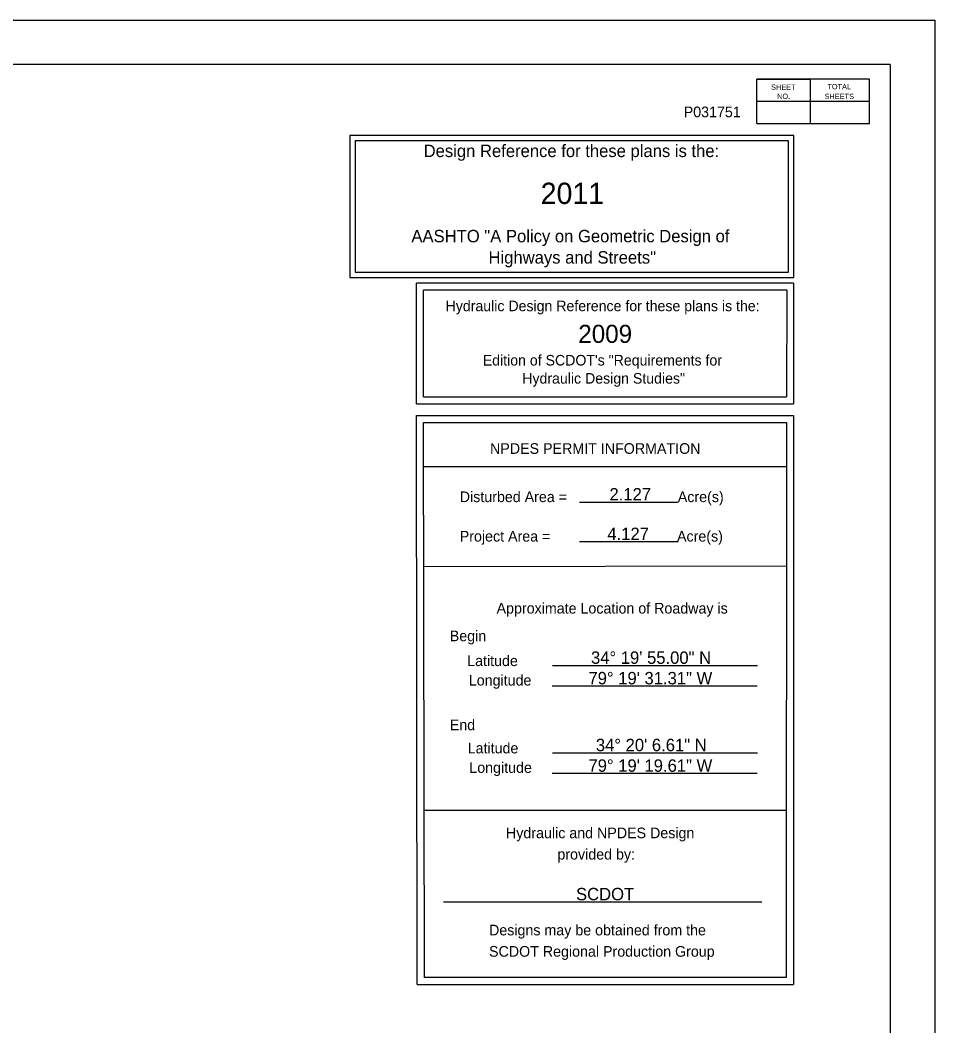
# Model space of a CAD drawing. Extents: x 178032 to 180477, y 178203 to 180757.
# Drawn here: x 179313 to 179828, y 178946 to 179513 of the extents above; entities that cross this region are included whole.
import ezdxf

# ---------------------------------------------------------------- set-up
doc = ezdxf.new("R2010")
doc.units = 0
for name, color, linetype in [('RD_SHT_Bndy', 7, 'Continuous'), ('RD_SHT_IplotShp', 7, 'Continuous'), ('RD_SHT_Snap', 7, 'Continuous'), ('RD_SHT_TX', 7, 'Continuous'), ('RD_TX_TitleSht', 7, 'Continuous')]:
    doc.layers.add(name, color=color, linetype=linetype)

msp = doc.modelspace()

# ---------------------------------------------------------------- linework, layer by layer
at = {"layer": 'RD_SHT_Bndy'}
for p, q in [((178048.25, 179512.54), (179808.23, 179512.54)), ((179803.28, 179487.54), (178128.38, 179487.54)), ((179803.38, 178437.54), (179803.38, 179487.59)), ((179791.53, 179479.34), (179728.03, 179479.34)), ((179728.03, 179454.34), (179728.03, 179479.34)), ((179728.03, 179479.34), (179758.03, 179479.34)), ((179758.03, 179479.34), (179758.03, 179454.34)), ((179791.53, 179454.34), (179791.53, 179479.34)), ((179728.4, 179466.84), (179791.18, 179466.84)), ((179728.03, 179454.34), (179791.53, 179454.34)), ((179536.35, 179296.45), (179536.28, 179364.44)), ((179748.8, 179364.44), (179536.28, 179364.44)), ((179748.8, 179364.44), (179748.78, 179296.5)), ((179540.32, 179300.4), (179540.23, 179360.5)), ((179744.88, 179360.5), (179540.23, 179360.5)), ((179744.88, 179360.5), (179744.85, 179300.45)), ((179540.32, 179300.4), (179744.85, 179300.45)), ((179536.35, 179296.45), (179748.78, 179296.5)), ((179536.35, 179289.82), (179748.78, 179289.87)), ((179536.72, 178969.44), (179536.35, 179289.82)), ((179748.78, 179289.87), (179748.7, 178969.44)), ((179540.33, 179285.82), (179744.84, 179285.99)), ((179540.8, 178973.38), (179540.33, 179285.82)), ((179744.84, 179285.99), (179744.67, 178973.3)), ((179540.48, 179261.07), (179744.8, 179261.04)), ((179628.25, 179241.09), (179683.8, 179241.09)), ((179628.25, 179218.86), (179683.8, 179218.86)), ((179540.45, 179204.9), (179744.66, 179205.17)), ((179612.97, 179149.13), (179728.52, 179149.13)), ((179612.77, 179137.54), (179728.33, 179137.54)), ((179612.97, 179099.91), (179728.52, 179099.91)), ((179612.77, 179088.32), (179728.33, 179088.32)), ((179744.77, 179067.32), (179540.66, 179067.32)), ((179551.52, 179015.91), (179730.96, 179015.91)), ((179744.67, 178973.3), (179540.8, 178973.38))]:
    msp.add_line(p, q, dxfattribs=at)
msp.add_lwpolyline([(179536.72, 178969.44), (179748.7, 178969.44)], dxfattribs=at)
at = {"layer": 'RD_SHT_IplotShp'}
msp.add_lwpolyline([(178032.38, 179512.54), (179828.38, 179512.54), (179828.38, 178412.54), (178032.38, 178412.54)], close=True, dxfattribs=at)
at = {"layer": 'RD_SHT_Snap'}
msp.add_line((179828.38, 179512.54), (179828.38, 178412.54), dxfattribs=at)
at = {"layer": 'RD_TX_TitleSht'}
for points in [[(179498.83, 179367.52), (179748.83, 179367.52), (179748.83, 179447.52), (179498.83, 179447.52)], [(179501.83, 179370.52), (179745.83, 179370.52), (179745.83, 179444.52), (179501.83, 179444.52)]]:
    msp.add_lwpolyline(points, close=True, dxfattribs=at)

# ---------------------------------------------------------------- texts
at = {"layer": 'RD_SHT_TX'}
for s, height, p in [('SHEET', 3, (179736.09, 179473.27)), ('TOTAL', 3, (179767.81, 179473.59)), ('NO.', 3, (179739.49, 179468.12)), ('SHEETS', 3, (179766.22, 179468.07)), ('NPDES PERMIT INFORMATION', 6, (179577.76, 179268.26)), ('Disturbed Area =                            Acre(s)', 6, (179560.71, 179241.07)), ('Project Area =                                Acre(s)', 6, (179560.71, 179218.85)), ('Approximate Location of Roadway is', 6, (179581.46, 179178.31)), ('Begin', 6, (179555.09, 179162.72)), ('Latitude', 6, (179564.89, 179148.72)), ('Longitude', 6, (179565.82, 179137.76)), ('End', 6, (179555.09, 179112.61)), ('Latitude', 6, (179565.18, 179099.54)), ('Longitude', 6, (179566.1, 179088.58)), ('Hydraulic and NPDES Design', 6, (179586.75, 179051.76)), ('             provided by:', 6, (179586.75, 179039.75)), ('Designs may be obtained from the ', 6, (179577.2, 178997.04)), ('SCDOT Regional Production Group', 6, (179577.2, 178985.03))]:
    msp.add_text(s, height=height, dxfattribs=at).set_placement(p)
at = {"layer": 'RD_TX_TitleSht'}
for s, height, p in [('P031751', 6, (179686.88, 179457.84)), ('Design Reference for these plans is the:', 7, (179540.36, 179435.4)), ('2011', 12, (179606.32, 179408.98)), ('AASHTO "A Policy on Geometric Design of ', 7, (179533.47, 179387.4)), ('Highways and Streets"', 7, (179576.9, 179375.4)), ('Hydraulic Design Reference for these plans is the:', 5.9493, (179552.74, 179348.6)), ('2009', 10.199, (179627.47, 179330.74)), ('Edition of SCDOT\'s "Requirements for ', 5.9493, (179573.67, 179318.01)), ('Hydraulic Design Studies"', 5.9493, (179595.92, 179307.81)), ('2.127', 7, (179645.04, 179241.99)), ('4.127', 7, (179643.86, 179219.69)), ('34%%D 19\' 55.00" N', 7, (179634.66, 179149.98)), ('79%%D 19\' 31.31" W', 7, (179633.23, 179138.42)), ('34%%D 20\' 6.61" N', 7, (179637.38, 179100.77)), ('79%%D 19\' 19.61" W', 7, (179633.23, 179089.18)), ('SCDOT', 7, (179626.21, 179016.8))]:
    msp.add_text(s, height=height, dxfattribs=at).set_placement(p)

doc.saveas('drawing.dxf')
